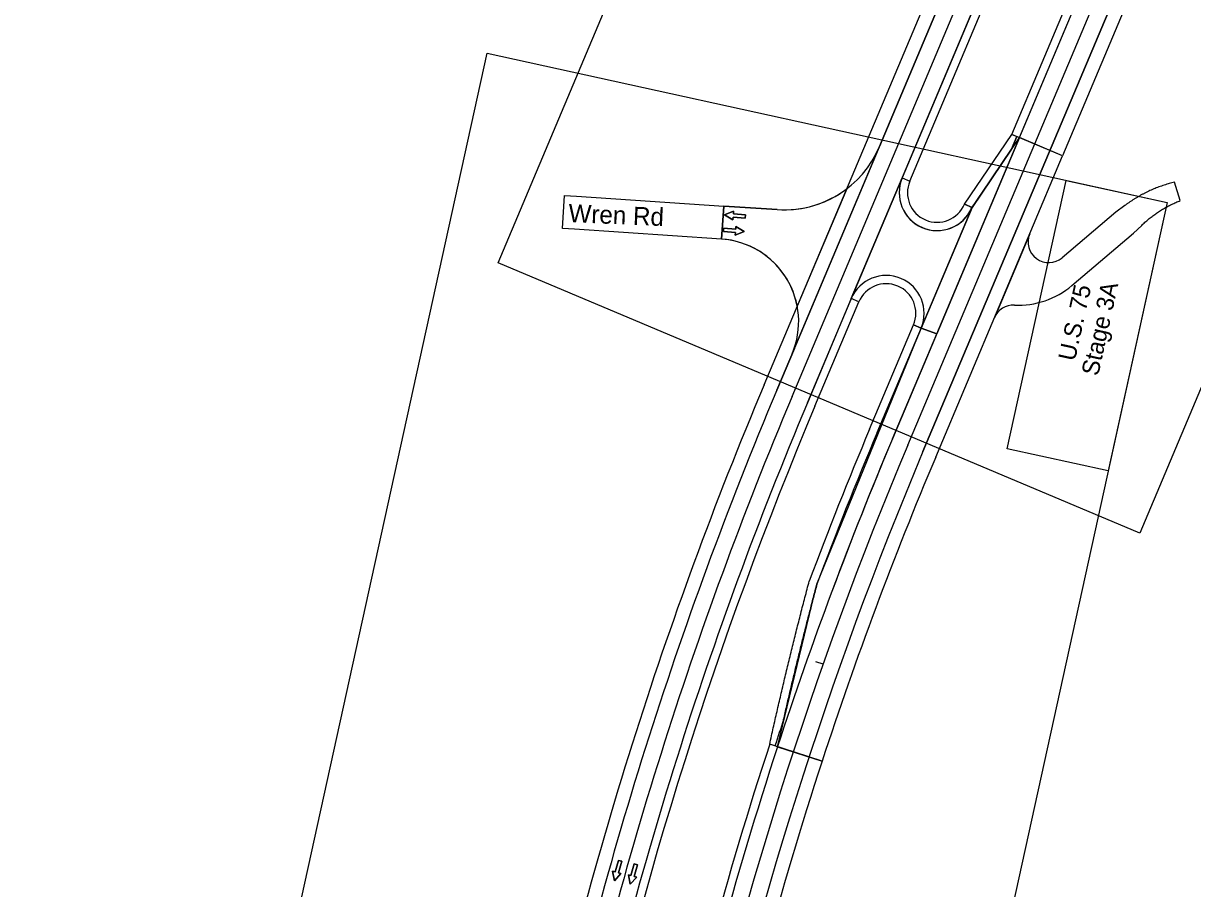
# Model space of a CAD drawing. Extents: x 14104283 to 14129344, y 8637090 to 8673339.
# Drawn here: x 14108596 to 14109444, y 8645070 to 8645697 of the extents above; entities that cross this region are included whole.
import ezdxf

# ---------------------------------------------------------------- set-up
doc = ezdxf.new("R2010")
doc.units = 0
for name, color, linetype in [('Cell', 7, 'Continuous'), ('Default', 7, 'Continuous'), ('dsnNonPlotable', 7, 'Continuous'), ('dsnPaintExistingBrokenLaneLineWhite', 7, 'Continuous'), ('dsnPaintExistingEdgeLineRightWhite', 7, 'Continuous'), ('dsnPaintExistingLaneLineWhite', 7, 'Continuous'), ('dsnPaintPlaceBrokenLineWhite', 7, 'Continuous'), ('dsnPaintPlaceEdgeLineLeftYellow', 7, 'Continuous'), ('dsnPaintPlaceEdgeLineRightWhite', 7, 'Continuous'), ('dsnShadingGranular', 7, 'Continuous'), ('dsnShadingPaved', 7, 'Continuous'), ('dsnStgShadingPrevPav', 7, 'Continuous'), ('dsnTextFinalPlan', 7, 'Continuous'), ('dsnTextOverlapEven', 7, 'Continuous'), ('TextAlignmentLrg', 7, 'Continuous')]:
    doc.layers.add(name, color=color, linetype=linetype)

msp = doc.modelspace()

# ---------------------------------------------------------------- linework, layer by layer
at = {"layer": 'Cell'}
for points in [[(14109119.8, 8645558.61), (14109119.6, 8645556.12), (14109110.88, 8645556.82), (14109110.73, 8645554.95), (14109104.75, 8645558.56), (14109111.23, 8645561.18), (14109111.08, 8645559.31)], [(14109103.82, 8645546.48), (14109104.02, 8645548.97), (14109112.74, 8645548.27), (14109112.89, 8645550.14), (14109118.87, 8645546.53), (14109112.39, 8645543.91), (14109112.54, 8645545.78)], [(14109027.78, 8645090.37), (14109030.18, 8645089.67), (14109027.72, 8645081.27), (14109029.52, 8645080.74), (14109024.76, 8645075.62), (14109023.52, 8645082.5), (14109025.32, 8645081.97)], [(14109039.23, 8645087.85), (14109041.63, 8645087.15), (14109039.17, 8645078.75), (14109040.97, 8645078.23), (14109036.21, 8645073.11), (14109034.97, 8645079.98), (14109036.77, 8645079.46)]]:
    msp.add_lwpolyline(points, close=True, dxfattribs=at)
for points in [[(14109111.08, 8645559.31), (14109111.23, 8645561.18), (14109104.75, 8645558.56), (14109110.73, 8645554.95), (14109110.88, 8645556.82), (14109119.6, 8645556.12), (14109119.8, 8645558.61), (14109111.08, 8645559.31)], [(14109112.54, 8645545.78), (14109112.39, 8645543.91), (14109118.87, 8645546.53), (14109112.89, 8645550.14), (14109112.74, 8645548.27), (14109104.02, 8645548.97), (14109103.82, 8645546.48), (14109112.54, 8645545.78)], [(14109025.32, 8645081.97), (14109023.52, 8645082.5), (14109024.76, 8645075.62), (14109029.52, 8645080.74), (14109027.72, 8645081.27), (14109030.18, 8645089.67), (14109027.78, 8645090.37), (14109025.32, 8645081.97)], [(14109036.77, 8645079.46), (14109034.97, 8645079.98), (14109036.21, 8645073.11), (14109040.97, 8645078.23), (14109039.17, 8645078.75), (14109041.63, 8645087.15), (14109039.23, 8645087.85), (14109036.77, 8645079.46)]]:
    msp.add_lwpolyline(points, dxfattribs=at)
at = {"layer": 'Default'}
for points in [[(14118413.25, 8667444.25), (14110818.39, 8649409.15), (14109142.61, 8645431.44)], [(14109164.73, 8645422.12), (14110840.51, 8649399.84), (14118435.37, 8667434.94)]]:
    msp.add_lwpolyline(points, dxfattribs=at)
for radius in [2968, 2944]:
    msp.add_arc((14111877.8, 8644279.13), radius, 157.1547, 167.84877, dxfattribs=at)
at = {"layer": 'dsnNonPlotable'}
for points in [[(14108940.51, 8645523.76), (14109549.08, 8646968.3), (14110014.46, 8646772.24), (14109405.89, 8645327.7)], [(14108596.11, 8644144.86), (14108932.49, 8645675.84), (14109425.73, 8645567.47), (14109089.34, 8644036.49)]]:
    msp.add_lwpolyline(points, close=True, dxfattribs=at)
at = {"layer": 'dsnPaintExistingBrokenLaneLineWhite'}
msp.add_line((14109153.67, 8645426.78), (14110829.45, 8649404.5), dxfattribs=at)
msp.add_arc((14111877.8, 8644279.13), 2956, 157.1547, 167.84877, dxfattribs=at)
at = {"layer": 'dsnPaintExistingEdgeLineRightWhite'}
msp.add_line((14109248.59, 8645386.79), (14110924.38, 8649364.51), dxfattribs=at)
msp.add_arc((14111877.79, 8644279.13), 2853, 157.1547, 167.84877, dxfattribs=at)
at = {"layer": 'dsnPaintExistingLaneLineWhite'}
msp.add_line((14109226.48, 8645396.11), (14109258.54, 8645472.23), dxfattribs=at)
msp.add_arc((14111877.79, 8644279.13), 2877, 157.1547, 159.50271, dxfattribs=at)
at = {"layer": 'dsnPaintPlaceBrokenLineWhite'}
msp.add_line((14109237.53, 8645391.45), (14110075.43, 8647380.31), dxfattribs=at)
msp.add_arc((14111877.79, 8644279.13), 2865, 157.1547, 167.84877, dxfattribs=at)
at = {"layer": 'dsnPaintPlaceEdgeLineLeftYellow'}
for p, q in [((14109318.52, 8645614.6), (14110902.26, 8649373.83)), ((14109283.61, 8645562.93), (14109318.29, 8645614.05)), ((14109196.6, 8645497.77), (14109164.73, 8645422.12)), ((14109171.7, 8645290.75), (14109247.29, 8645476.42)), ((14109143.12, 8645172.82), (14109171.7, 8645290.75))]:
    msp.add_line(p, q, dxfattribs=at)
msp.add_lwpolyline([(14111383.58, 8650689.44), (14110840.51, 8649399.84), (14109233.49, 8645585.32)], dxfattribs=at)
for centre, radius, start, end in [((14109258.83, 8645574.64), 27.5, 157.1547, 335.84151), ((14109221.94, 8645487.09), 27.5, 67.1547, 157.1547), ((14109221.94, 8645487.09), 27.5, 337.1547, 67.1547), ((14111877.8, 8644279.13), 2944, 157.1547, 167.84877), ((14111877.79, 8644279.13), 2877, 161.90302, 167.84877)]:
    msp.add_arc(centre, radius, start, end, dxfattribs=at)
at = {"layer": 'dsnPaintPlaceEdgeLineRightWhite'}
msp.add_line((14109155.29, 8645461.54), (14109142.61, 8645431.44), dxfattribs=at)
msp.add_lwpolyline([(14111344.56, 8650658.61), (14110818.39, 8649409.15), (14109217.02, 8645608.05)], dxfattribs=at)
msp.add_arc((14111877.8, 8644279.13), 2968, 157.1547, 167.84877, dxfattribs=at)
at = {"layer": 'dsnShadingGranular'}
msp.add_line((14109325.98, 8645544.73), (14109300.38, 8645483.96), dxfattribs=at)
at = {"layer": 'dsnShadingPaved'}
for p, q in [((14109258.54, 8645472.23), (14110902.26, 8649373.83)), ((14110924.38, 8649364.51), (14109248.59, 8645386.79)), ((14109318.29, 8645614.05), (14109258.54, 8645472.23)), ((14109283.61, 8645562.93), (14109318.29, 8645614.05)), ((14109153.74, 8645457.84), (14109217.02, 8645608.05)), ((14109196.6, 8645497.77), (14109233.49, 8645585.32)), ((14109104.08, 8645564.95), (14109102.47, 8645541)), ((14109142.87, 8645562.34), (14109104.08, 8645564.95)), ((14109171.7, 8645290.75), (14109247.29, 8645476.42)), ((14109247.29, 8645476.42), (14109258.54, 8645472.23)), ((14109258.54, 8645472.23), (14109247.29, 8645476.42)), ((14109143.12, 8645172.82), (14109171.7, 8645290.75))]:
    msp.add_line(p, q, dxfattribs=at)
for centre, radius, start, end in [((14109147.9, 8645637.17), 75, 266.1547, 337.1547), ((14109258.83, 8645574.64), 27.5, 157.1547, 247.1547), ((14109258.83, 8645574.64), 27.5, 247.1547, 335.84151), ((14109098.44, 8645481.13), 60, 337.1547, 86.1547), ((14109221.94, 8645487.09), 27.5, 67.1547, 157.1547), ((14109221.94, 8645487.09), 27.5, 337.1547, 67.1547), ((14111877.79, 8644279.13), 2853, 157.1547, 167.84877), ((14111877.79, 8644279.13), 2877, 161.90302, 167.84877)]:
    msp.add_arc(centre, radius, start, end, dxfattribs=at)
at = {"layer": 'dsnStgShadingPrevPav'}
for p, q in [((14109133.4, 8645435.32), (14110809.18, 8649413.03)), ((14110818.39, 8649409.15), (14109142.61, 8645431.44)), ((14109318.52, 8645614.6), (14109226.48, 8645396.11)), ((14109318.52, 8645614.6), (14109226.48, 8645396.11)), ((14109312.8, 8645606.16), (14109316.68, 8645615.38)), ((14109316.68, 8645615.38), (14109318.52, 8645614.6)), ((14109349.86, 8645601.4), (14109318.52, 8645614.6)), ((14109155.29, 8645461.54), (14109217.02, 8645608.05)), ((14109284.17, 8645563.96), (14109312.8, 8645606.16)), ((14109257.81, 8645382.91), (14109349.86, 8645601.4)), ((14109196.6, 8645497.77), (14109233.49, 8645585.32)), ((14109233.49, 8645585.32), (14109196.6, 8645497.77)), ((14109233.49, 8645585.32), (14109239.01, 8645582.99)), ((14109435.19, 8645568.84), (14109431.12, 8645582.24)), ((14109193.28, 8645577.45), (14109157.4, 8645492.29)), ((14109102.47, 8645541), (14109104.08, 8645564.95)), ((14109104.08, 8645564.95), (14109142.87, 8645562.34)), ((14109215.42, 8645400.77), (14109284.17, 8645563.96)), ((14109284.17, 8645563.96), (14109247.29, 8645476.42)), ((14109278.64, 8645566.29), (14109284.17, 8645563.96)), ((14109325.98, 8645544.73), (14109300.38, 8645483.96)), ((14109356.61, 8645507.27), (14109401.37, 8645545.2)), ((14109401.37, 8645545.2), (14109407.22, 8645550.87)), ((14109196.6, 8645497.77), (14109164.73, 8645422.12)), ((14109196.6, 8645497.77), (14109164.73, 8645422.12)), ((14109170.26, 8645419.79), (14109202.13, 8645495.44)), ((14109202.13, 8645495.44), (14109196.6, 8645497.77)), ((14109202.13, 8645495.44), (14109196.6, 8645497.77)), ((14109209.89, 8645403.09), (14109241.76, 8645478.75)), ((14109247.29, 8645476.42), (14109215.42, 8645400.77)), ((14109247.29, 8645476.42), (14109241.76, 8645478.75)), ((14109241.76, 8645478.75), (14109247.29, 8645476.42)), ((14109142.61, 8645431.44), (14109155.29, 8645461.54)), ((14109175.44, 8645162.26), (14109137.42, 8645174.69)), ((14109141.22, 8645173.44), (14109137.42, 8645174.69)), ((14109143.12, 8645172.82), (14109141.22, 8645173.44)), ((14109143.12, 8645172.82), (14109175.44, 8645162.26))]:
    msp.add_line(p, q, dxfattribs=at)
for points in [[(14109239.01, 8645582.99), (14111389.11, 8650687.11), (14111383.58, 8650689.44), (14109233.49, 8645585.32)], [(14109313, 8645616.93), (14110622.7, 8648725.72), (14110659.7, 8648710.5), (14109349.86, 8645601.4)], [(14109278.64, 8645566.29), (14109313, 8645616.93), (14109316.68, 8645615.38), (14109312.8, 8645606.16), (14109284.17, 8645563.96)], [(14108987.25, 8645548.72), (14108988.7, 8645572.67), (14108997.4, 8645572.12), (14109104.08, 8645564.95), (14109102.47, 8645541), (14108995.79, 8645548.17)]]:
    msp.add_lwpolyline(points, close=True, dxfattribs=at)
for points in [[(14111383.58, 8650689.44), (14110840.51, 8649399.84), (14109233.49, 8645585.32)], [(14109217.02, 8645608.05), (14110818.39, 8649409.15), (14111344.56, 8650658.61)], [(14109395, 8645565.3), (14109388.44, 8645560.45), (14109349.5, 8645527.46)]]:
    msp.add_lwpolyline(points, dxfattribs=at)
for centre, radius, start, end in [((14109258.83, 8645574.64), 21.5, 157.1547, 247.1547), ((14109147.9, 8645637.17), 75, 266.1547, 307.22827), ((14109258.83, 8645574.64), 21.5, 247.1547, 337.1547), ((14109339.81, 8645538.91), 15, 157.1547, 310.2778), ((14109098.44, 8645481.13), 60, 10.71201, 86.1547), ((14109221.94, 8645487.09), 21.5, 67.1547, 157.1547), ((14109221.94, 8645487.09), 21.5, 337.1547, 67.1547), ((14109317.82, 8645553.05), 60, 267.23357, 310.2778), ((14109314.2, 8645478.13), 15, 87.23357, 157.1547), ((14111877.8, 8644279.13), 2978, 157.1547, 167.84877), ((14111877.8, 8644279.13), 2968, 157.1547, 167.84877), ((14111877.8, 8644279.13), 2968, 157.1547, 167.84877), ((14111877.8, 8644279.13), 2944, 157.1547, 167.84877), ((14111877.8, 8644279.13), 2944, 157.1547, 167.84877), ((14111877.8, 8644279.13), 2938, 157.1547, 167.84877), ((14111877.79, 8644279.13), 2895, 157.1547, 159.50271), ((14111877.79, 8644279.13), 2889, 157.1547, 159.50271), ((14111877.79, 8644279.13), 2889, 157.1547, 159.50271), ((14111877.79, 8644279.13), 2877, 157.1547, 161.90253), ((14111877.79, 8644279.13), 2877, 157.1547, 161.90253), ((14111877.79, 8644279.13), 2843, 157.1547, 161.90253), ((14111877.79, 8644279.13), 2879, 161.50256, 161.90253), ((14111877.79, 8644279.13), 2879, 161.50256, 161.90253), ((14111877.79, 8644279.13), 2883, 161.90253, 167.84877), ((14111877.79, 8644279.13), 2843, 161.90253, 167.84877)]:
    msp.add_arc(centre, radius, start, end, dxfattribs=at)
for points in [[(14109431.12, 8645582.24), (14109430.48, 8645582.08), (14109429.19, 8645581.77), (14109427.27, 8645581.25), (14109425.36, 8645580.69), (14109423.46, 8645580.1), (14109421.57, 8645579.46), (14109419.69, 8645578.78), (14109417.82, 8645578.07), (14109415.97, 8645577.31), (14109414.12, 8645576.52), (14109412.3, 8645575.69), (14109410.49, 8645574.81), (14109408.69, 8645573.91), (14109406.91, 8645572.96), (14109405.15, 8645571.98), (14109403.4, 8645570.95), (14109401.68, 8645569.9), (14109399.98, 8645568.8), (14109398.29, 8645567.67), (14109396.63, 8645566.51), (14109395.54, 8645565.7), (14109395, 8645565.3)], [(14109407.22, 8645550.87), (14109407.62, 8645551.25), (14109408.41, 8645552.02), (14109409.62, 8645553.14), (14109410.86, 8645554.24), (14109412.12, 8645555.32), (14109413.4, 8645556.37), (14109414.71, 8645557.39), (14109416.05, 8645558.39), (14109417.4, 8645559.37), (14109418.77, 8645560.31), (14109420.17, 8645561.23), (14109421.59, 8645562.13), (14109423.03, 8645562.99), (14109424.48, 8645563.83), (14109425.96, 8645564.64), (14109427.45, 8645565.41), (14109428.97, 8645566.16), (14109430.5, 8645566.88), (14109432.04, 8645567.57), (14109433.61, 8645568.23), (14109434.66, 8645568.64), (14109435.19, 8645568.84)], [(14109137.42, 8645174.69), (14109137.85, 8645176.66), (14109138.73, 8645180.61), (14109140.05, 8645186.54), (14109141.39, 8645192.46), (14109142.74, 8645198.38), (14109144.1, 8645204.29), (14109145.48, 8645210.21), (14109146.86, 8645216.13), (14109148.27, 8645222.04), (14109149.68, 8645227.95), (14109151.11, 8645233.86), (14109152.55, 8645239.77), (14109154, 8645245.67), (14109155.46, 8645251.58), (14109156.94, 8645257.48), (14109158.43, 8645263.38), (14109159.94, 8645269.28), (14109161.45, 8645275.17), (14109162.98, 8645281.07), (14109164.52, 8645286.96), (14109165.56, 8645290.89), (14109166.08, 8645292.85)], [(14109147.53, 8645192.53), (14109147.9, 8645194.17), (14109148.65, 8645197.45), (14109149.78, 8645202.37), (14109150.93, 8645207.29), (14109152.08, 8645212.21), (14109153.24, 8645217.13), (14109154.41, 8645222.05), (14109155.58, 8645226.96), (14109156.77, 8645231.88), (14109157.97, 8645236.79), (14109159.17, 8645241.7), (14109160.38, 8645246.61), (14109161.6, 8645251.52), (14109162.83, 8645256.43), (14109164.07, 8645261.34), (14109165.32, 8645266.24), (14109166.58, 8645271.15), (14109167.85, 8645276.05), (14109169.12, 8645280.95), (14109170.4, 8645285.85), (14109171.27, 8645289.12), (14109171.7, 8645290.75)], [(14109171.7, 8645290.75), (14109171.27, 8645289.12), (14109170.4, 8645285.85), (14109169.12, 8645280.95), (14109167.85, 8645276.05), (14109166.58, 8645271.15), (14109165.32, 8645266.24), (14109164.07, 8645261.34), (14109162.83, 8645256.43), (14109161.6, 8645251.52), (14109160.38, 8645246.61), (14109159.17, 8645241.7), (14109157.97, 8645236.79), (14109156.77, 8645231.88), (14109155.58, 8645226.96), (14109154.41, 8645222.05), (14109153.24, 8645217.13), (14109152.08, 8645212.21), (14109150.93, 8645207.29), (14109149.78, 8645202.37), (14109148.65, 8645197.45), (14109147.9, 8645194.17), (14109147.53, 8645192.53)]]:
    msp.add_open_spline(points, degree=3, dxfattribs=at)
at = {"layer": 'dsnTextOverlapEven'}
for points in [[(14109425.73, 8645567.47), (14109382.96, 8645372.83), (14109309.71, 8645388.93), (14109352.48, 8645583.57)], [(14109309.71, 8645388.93), (14109352.48, 8645583.57), (14109425.73, 8645567.47), (14109382.96, 8645372.83)]]:
    msp.add_lwpolyline(points, close=True, dxfattribs=at)
at = {"layer": 'TextAlignmentLrg'}
msp.add_line((14109176.12, 8645232.64), (14109170.97, 8645234.45), dxfattribs=at)

# ---------------------------------------------------------------- texts
at = {"layer": 'dsnTextFinalPlan'}
msp.add_text('Wren Rd', height=13.125, rotation=357.6374, dxfattribs=at).set_placement((14108991.27, 8645553.28))
at = {"layer": 'dsnTextOverlapEven'}
for s, p in [('U.S. 75', (14109358.74, 8645451.91)), ('Stage 3A', (14109375.58, 8645441.15))]:
    msp.add_text(s, height=12.5, rotation=77.60784, dxfattribs=at).set_placement(p)

doc.saveas('drawing.dxf')
